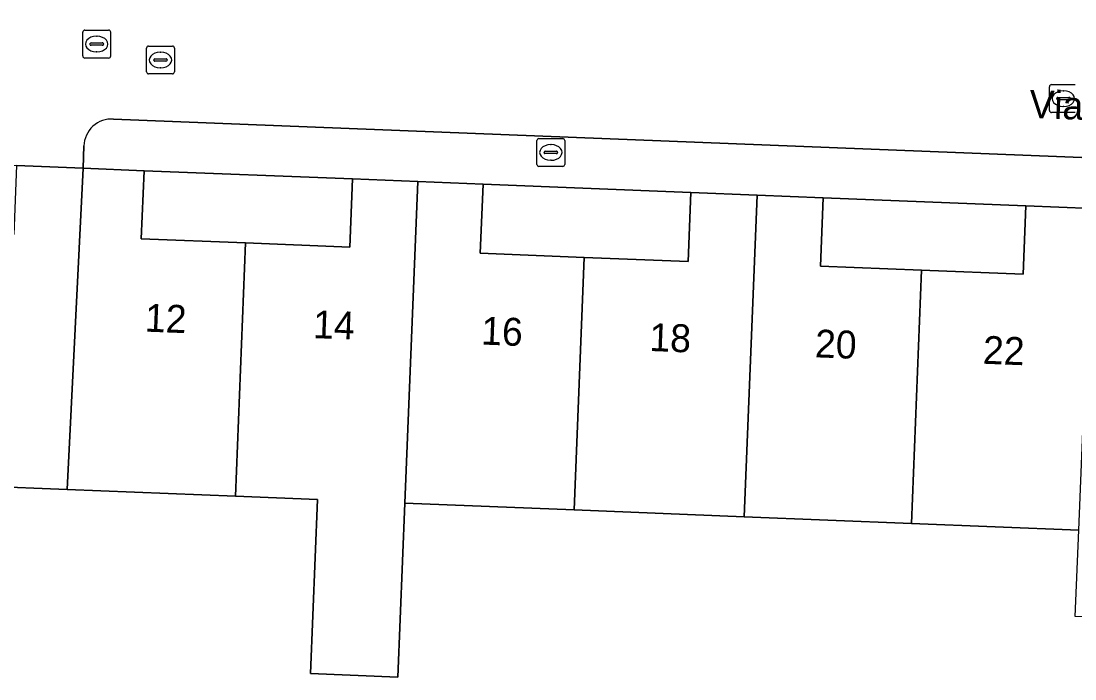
# Model space of a CAD drawing. Extents: x 160786 to 161429, y 386828 to 387485.
# Drawn here: x 161029.49 to 161067.25, y 387170.31 to 387193.89 of the extents above; entities that cross this region are included whole.
import ezdxf

# ---------------------------------------------------------------- set-up
doc = ezdxf.new("R2010")
doc.units = 0
for name, color, linetype in [('IMGEO_Brandkraan', 7, 'Continuous'), ('IMGEO_Erf', 7, 'Continuous'), ('IMGEO_Kolk', 7, 'Continuous'), ('IMGEO_Openbare_ruimte_label', 7, 'Continuous'), ('IMGEO_Pand', 7, 'Continuous'), ('IMGEO_Pand_nummerreeks', 7, 'Continuous'), ('IMGEO_Rijbaan_lokaal_open', 7, 'Continuous'), ('IMGEO_Rioolput', 7, 'Continuous'), ('IMGEO_Voetpad_open', 7, 'Continuous')]:
    doc.layers.add(name, color=color, linetype=linetype)

msp = doc.modelspace()

# ---------------------------------------------------------------- linework, layer by layer
at = {"layer": 'IMGEO_Brandkraan'}
for p, q in [((161047.973, 387188.755), (161047.973, 387189.607)), ((161048.048, 387189.681), (161048.9, 387189.681)), ((161048.461, 387189.461), (161048.486, 387189.461)), ((161048.974, 387189.607), (161048.974, 387188.755)), ((161048.232, 387189.175), (161048.232, 387189.187)), ((161048.67, 387189.138), (161048.272, 387189.138)), ((161048.275, 387189.224), (161048.673, 387189.224)), ((161048.716, 387189.187), (161048.716, 387189.175)), ((161048.484, 387188.901), (161048.459, 387188.901)), ((161048.9, 387188.681), (161048.048, 387188.681))]:
    msp.add_line(p, q, dxfattribs=at)
for points in [[(161047.973, 387188.755), (161047.973, 387189.607)], [(161048.048, 387189.681), (161048.9, 387189.681)], [(161048.974, 387189.607), (161048.974, 387188.755)], [(161048.9, 387188.681), (161048.048, 387188.681)]]:
    msp.add_lwpolyline(points, dxfattribs=at)
for centre, radius, start, end in [((161048.05, 387189.605), 0.0765, 91.552, 178.448), ((161048.05, 387189.605), 0.0765, 91.552, 178.448), ((161048.898, 387189.605), 0.0765, 1.552, 88.448), ((161048.898, 387189.605), 0.0765, 1.552, 88.448), ((161048.272, 387189.184), 0.0403, 85.8775, 175.7526), ((161048.269, 387189.174), 0.0366, 178.938, 274.7102), ((161048.673, 387189.181), 0.043, 264.8664, 352.4533), ((161048.677, 387189.186), 0.0386, 1.7309, 96.639), ((161048.05, 387188.757), 0.0765, 181.552, 268.448), ((161048.05, 387188.757), 0.0765, 181.552, 268.448), ((161048.898, 387188.757), 0.0765, 271.552, 358.448), ((161048.898, 387188.757), 0.0765, 271.552, 358.448)]:
    msp.add_arc(centre, radius, start, end, dxfattribs=at)
for centre, major_axis, ratio, start_param, end_param in [((161048.46, 387189.181), (-0.387, 0.002), 0.722429, 4.712389, 7.853982), ((161048.485, 387189.181), (-0.39, 0.002), 0.717154, 1.570796, 4.712389)]:
    msp.add_ellipse(centre, major_axis=major_axis, ratio=ratio, start_param=start_param, end_param=end_param, dxfattribs=at)
at = {"layer": 'IMGEO_Erf'}
for points in [[(161033.897, 387188.525), (161033.799, 387186.089), (161037.535, 387185.938), (161041.27, 387185.788), (161041.369, 387188.239)], [(161046.047, 387188.05), (161045.947, 387185.57), (161049.67, 387185.42), (161053.394, 387185.269), (161053.494, 387187.747)], [(161058.231, 387187.556), (161058.132, 387185.108), (161061.762, 387184.962), (161065.397, 387184.815), (161065.496, 387187.273)]]:
    msp.add_lwpolyline(points, close=True, dxfattribs=at)
msp.add_lwpolyline([(161097.233, 387163.345), (161097.659, 387174.419), (161091.385, 387174.672), (161085.378, 387174.915), (161079.404, 387175.156), (161073.408, 387175.398), (161073.283, 387172.301), (161067.264, 387172.544), (161067.389, 387175.64), (161061.396, 387175.882), (161055.397, 387176.124), (161049.305, 387176.37), (161043.243, 387176.615), (161042.991, 387170.375), (161039.859, 387170.501), (161040.111, 387176.741), (161037.169, 387176.86), (161031.147, 387177.103), (161025.183, 387177.344), (161019.173, 387177.586), (161013.147, 387177.829), (161007.179, 387178.07), (161001.282, 387178.308), (161000.924, 387167.442)], dxfattribs=at)
at = {"layer": 'IMGEO_Kolk'}
for p, q in [((161031.699, 387192.64), (161031.699, 387193.492)), ((161031.774, 387193.566), (161032.626, 387193.566)), ((161032.187, 387193.346), (161032.212, 387193.346)), ((161032.7, 387193.492), (161032.7, 387192.64)), ((161031.958, 387193.06), (161031.958, 387193.072)), ((161032.396, 387193.023), (161031.998, 387193.023)), ((161032.001, 387193.109), (161032.399, 387193.109)), ((161032.442, 387193.072), (161032.442, 387193.06)), ((161032.626, 387192.566), (161031.774, 387192.566)), ((161032.21, 387192.786), (161032.185, 387192.786))]:
    msp.add_line(p, q, dxfattribs=at)
for points in [[(161031.699, 387192.64), (161031.699, 387193.492)], [(161031.774, 387193.566), (161032.626, 387193.566)], [(161032.7, 387193.492), (161032.7, 387192.64)], [(161032.626, 387192.566), (161031.774, 387192.566)]]:
    msp.add_lwpolyline(points, dxfattribs=at)
for centre, radius, start, end in [((161031.776, 387193.49), 0.0765, 91.552, 178.448), ((161031.776, 387193.49), 0.0765, 91.552, 178.448), ((161032.624, 387193.49), 0.0765, 1.552, 88.448), ((161032.624, 387193.49), 0.0765, 1.552, 88.448), ((161031.998, 387193.069), 0.0403, 85.8775, 175.7526), ((161031.995, 387193.059), 0.0366, 178.938, 274.7102), ((161032.399, 387193.066), 0.043, 264.8664, 352.4533), ((161032.403, 387193.071), 0.0386, 1.7309, 96.639), ((161031.776, 387192.642), 0.0765, 181.552, 268.448), ((161031.776, 387192.642), 0.0765, 181.552, 268.448), ((161032.624, 387192.642), 0.0765, 271.552, 358.448), ((161032.624, 387192.642), 0.0765, 271.552, 358.448)]:
    msp.add_arc(centre, radius, start, end, dxfattribs=at)
for centre, major_axis, ratio, start_param, end_param in [((161032.186, 387193.066), (-0.387, 0.002), 0.722429, 4.712389, 7.853982), ((161032.211, 387193.066), (-0.39, 0.002), 0.717154, 1.570796, 4.712389)]:
    msp.add_ellipse(centre, major_axis=major_axis, ratio=ratio, start_param=start_param, end_param=end_param, dxfattribs=at)
at = {"layer": 'IMGEO_Pand'}
for points in [[(161029.331, 387188.71), (161029.231, 387186.239), (161025.548, 387186.388), (161025.183, 387177.344), (161031.147, 387177.103), (161031.71, 387188.614)], [(161031.71, 387188.614), (161031.147, 387177.103), (161037.169, 387176.86), (161037.535, 387185.938), (161033.799, 387186.089), (161033.897, 387188.525)], [(161043.708, 387188.145), (161041.369, 387188.239), (161041.27, 387185.788), (161037.535, 387185.938), (161037.169, 387176.86), (161040.111, 387176.741), (161039.859, 387170.501), (161042.991, 387170.375), (161043.243, 387176.615)], [(161043.708, 387188.145), (161043.243, 387176.615), (161049.305, 387176.37), (161049.67, 387185.42), (161045.947, 387185.57), (161046.047, 387188.05)], [(161053.494, 387187.747), (161053.394, 387185.269), (161049.67, 387185.42), (161049.305, 387176.37), (161055.397, 387176.124), (161055.862, 387187.652)], [(161055.862, 387187.652), (161055.397, 387176.124), (161061.396, 387175.882), (161061.762, 387184.962), (161058.132, 387185.108), (161058.231, 387187.556)], [(161065.496, 387187.273), (161065.397, 387184.815), (161061.762, 387184.962), (161061.396, 387175.882), (161067.389, 387175.64), (161067.855, 387187.178)]]:
    msp.add_lwpolyline(points, close=True, dxfattribs=at)
at = {"layer": 'IMGEO_Rijbaan_lokaal_open'}
for points in [[(161032.801, 387190.374), (161098.276, 387187.786), (161099.107, 387212.357)], [(161034.264, 387194.988), (161021.317, 387195.468), (161021.064, 387188.983), (161021.963, 387188.947), (161029.331, 387188.71), (161031.71, 387188.614), (161031.742, 387189.416)]]:
    msp.add_lwpolyline(points, dxfattribs=at)
msp.add_arc((161032.73, 387189.388), 0.989, 85.9011, 178.3656, dxfattribs=at)
at = {"layer": 'IMGEO_Rioolput'}
for p, q in [((161033.985, 387192.07), (161033.985, 387192.922)), ((161034.06, 387192.996), (161034.912, 387192.996)), ((161034.986, 387192.922), (161034.986, 387192.07)), ((161034.244, 387192.49), (161034.244, 387192.502)), ((161034.287, 387192.539), (161034.685, 387192.539)), ((161034.473, 387192.776), (161034.498, 387192.776)), ((161034.728, 387192.502), (161034.728, 387192.49)), ((161034.682, 387192.453), (161034.284, 387192.453)), ((161034.496, 387192.216), (161034.471, 387192.216)), ((161034.912, 387191.996), (161034.06, 387191.996)), ((161066.341, 387190.686), (161066.341, 387191.538)), ((161066.416, 387191.612), (161067.268, 387191.612)), ((161066.829, 387191.392), (161066.854, 387191.392)), ((161066.6, 387191.106), (161066.6, 387191.118)), ((161067.038, 387191.069), (161066.64, 387191.069)), ((161066.643, 387191.155), (161067.041, 387191.155)), ((161067.084, 387191.118), (161067.084, 387191.106)), ((161067.268, 387190.612), (161066.416, 387190.612)), ((161066.852, 387190.832), (161066.827, 387190.832))]:
    msp.add_line(p, q, dxfattribs=at)
for points in [[(161033.985, 387192.07), (161033.985, 387192.922)], [(161034.06, 387192.996), (161034.912, 387192.996)], [(161034.986, 387192.922), (161034.986, 387192.07)], [(161034.912, 387191.996), (161034.06, 387191.996)], [(161066.341, 387190.686), (161066.341, 387191.538)], [(161066.416, 387191.612), (161067.268, 387191.612)], [(161067.268, 387190.612), (161066.416, 387190.612)]]:
    msp.add_lwpolyline(points, dxfattribs=at)
for centre, radius, start, end in [((161034.062, 387192.92), 0.0765, 91.552, 178.448), ((161034.062, 387192.92), 0.0765, 91.552, 178.448), ((161034.91, 387192.92), 0.0765, 1.552, 88.448), ((161034.91, 387192.92), 0.0765, 1.552, 88.448), ((161034.284, 387192.499), 0.0403, 85.8775, 175.7526), ((161034.281, 387192.489), 0.0366, 178.938, 274.7102), ((161034.685, 387192.496), 0.043, 264.8664, 352.4533), ((161034.689, 387192.501), 0.0386, 1.7309, 96.639), ((161034.062, 387192.072), 0.0765, 181.552, 268.448), ((161034.062, 387192.072), 0.0765, 181.552, 268.448), ((161034.91, 387192.072), 0.0765, 271.552, 358.448), ((161034.91, 387192.072), 0.0765, 271.552, 358.448), ((161066.418, 387191.536), 0.0765, 91.552, 178.448), ((161066.418, 387191.536), 0.0765, 91.552, 178.448), ((161066.64, 387191.115), 0.0403, 85.8775, 175.7526), ((161066.637, 387191.105), 0.0366, 178.938, 274.7102), ((161067.041, 387191.112), 0.043, 264.8664, 352.4533), ((161067.045, 387191.117), 0.0386, 1.7309, 96.639), ((161066.418, 387190.688), 0.0765, 181.552, 268.448), ((161066.418, 387190.688), 0.0765, 181.552, 268.448)]:
    msp.add_arc(centre, radius, start, end, dxfattribs=at)
for centre, major_axis, ratio, start_param, end_param in [((161034.472, 387192.496), (-0.387, 0.002), 0.722429, 4.712389, 7.853982), ((161034.497, 387192.496), (-0.39, 0.002), 0.717154, 1.570796, 4.712389), ((161066.828, 387191.112), (-0.387, 0.002), 0.722429, 4.712389, 7.853982), ((161066.853, 387191.112), (-0.39, 0.002), 0.717154, 1.570796, 4.712389)]:
    msp.add_ellipse(centre, major_axis=major_axis, ratio=ratio, start_param=start_param, end_param=end_param, dxfattribs=at)
at = {"layer": 'IMGEO_Voetpad_open'}
msp.add_lwpolyline([(161031.742, 387189.416), (161031.71, 387188.614), (161033.897, 387188.525), (161041.369, 387188.239), (161043.708, 387188.145), (161046.047, 387188.05), (161053.494, 387187.747), (161055.862, 387187.652), (161058.231, 387187.556), (161065.496, 387187.273), (161067.855, 387187.178), (161070.215, 387187.083), (161077.536, 387186.834), (161079.872, 387186.74), (161082.211, 387186.646), (161089.478, 387186.343), (161091.852, 387186.247), (161094.224, 387186.152), (161098.215, 387185.98), (161098.276, 387187.786), (161032.801, 387190.374)], dxfattribs=at)
msp.add_arc((161032.73, 387189.388), 0.989, 85.9011, 178.3656, dxfattribs=at)

# ---------------------------------------------------------------- texts
at = {"layer": 'IMGEO_Openbare_ruimte_label'}
msp.add_text('Viandenhof', height=1, rotation=357.8789, dxfattribs=at).set_placement((161065.605, 387190.423))
at = {"layer": 'IMGEO_Pand_nummerreeks'}
for s, rotation, p in [('12', 357.8058, (161033.913, 387182.76)), ('14', 357.8056, (161039.94, 387182.528)), ('16', 357.8058, (161045.964, 387182.297)), ('18', 357.8058, (161051.991, 387182.066)), ('20', 357.8058, (161057.925, 387181.839)), ('22', 357.8058, (161063.943, 387181.609))]:
    msp.add_text(s, height=1, rotation=rotation, dxfattribs=at).set_placement(p)

doc.saveas('drawing.dxf')
